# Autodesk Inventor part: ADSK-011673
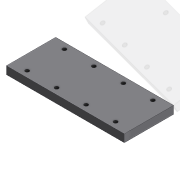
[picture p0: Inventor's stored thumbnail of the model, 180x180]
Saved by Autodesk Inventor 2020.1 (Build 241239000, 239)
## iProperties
Created: 2000-02
Part Number: ADSK-011673
Material: Pearson HRS
Document SubType Name: Modeling
Description: PLT-08,FH,AX,03,060,025,(8)C,CLAMP PLATE
Designer: glanglot
Density: 7.83 g/cm^3
Appearance: Métal - Acier
Mass: 743.857 g
Surface Area: 245.46 cm^2
Volume: 95.0009 cm^3
Control State: 0
Checked Out: False
Master: False
Shininess: 25.0
Length Units: 11269
Angle Units: 11279
Time Units: 11290
Mass Units: 11283
Length Display Precision: 3
Angle Display Precision: 2
Compacted: True
Cutlength: 6.0
Material Desc: FLAT,HRS,0.375X02.500
Material_Number: A084404
Dimensions: 152x10x63,5 mm
Mass: 0,744 kg
DocNumber: ADSK-011673.ipt
Folder: 01 - Themengebiete\Simplification\01 - Packaging machine\
VDS_Category: 3D Komponenten
Density: 7.83
Volumn: 90.69395060180393
Area: 243.48020198565166
PropertySet Name: Model Information
Author: glanglot
Revision Number: -
Title: plate
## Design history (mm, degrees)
node "Solide1"
  node "Extrusion2" dims "d4" = 63.5, "d5" = 0
  node "Hole1" dims "d10" = 4.917, "d11" = 9.525, "d12" = 6.35, "d13" = 60 deg, "d14" = 17.1, "d15" = 118 deg, "d31" = 12
sketch "Sketch1"
  geometry: L1 (-76, -5)-(76, -5); L2 (76, -5)-(76, 5); L3 (76, 5)-(-76, 5); L4 (-76, 5)-(-76, -5); 3 further points
  constraints: 8 end point, 2 midpoint, 2 parallel, 1 horizontal, 1 horizontal alignment, 1 perpendicular, 1 vertical alignment
  dimensions: "d0" = 152 distance between parallel lines of L4 L2; "d1" = 10 distance between parallel lines of L3 L1
sketch "Sketch2"
  geometry: L1 (152, 63.5)-(0, 63.5) reference; L2 (0, 0)-(0, 63.5) reference; L3 (19, 55.75)-(133, 55.75); L4 (133, 55.75)-(133, 7.75); L5 (133, 7.75)-(19, 7.75); L6 (19, 7.75)-(19, 55.75); 11 further points
  constraints: 8 end point, 4 midpoint, 4 point on line, 3 coincident, 3 vertical alignment, 2 parallel, 1 horizontal, 1 horizontal alignment, 1 perpendicular
  dimensions: "d27" = 48 distance of L5.end L3.start; "d28" = 38 distance of point (95, 55.75) point (57, 55.75); "d29" = 38 distance from line of L6 point (57, 55.75) (= d28); "d30" = 38 distance of L3.end point (95, 55.75) (= d28)
node "Corps solides"
node "Corps surfaciques"
